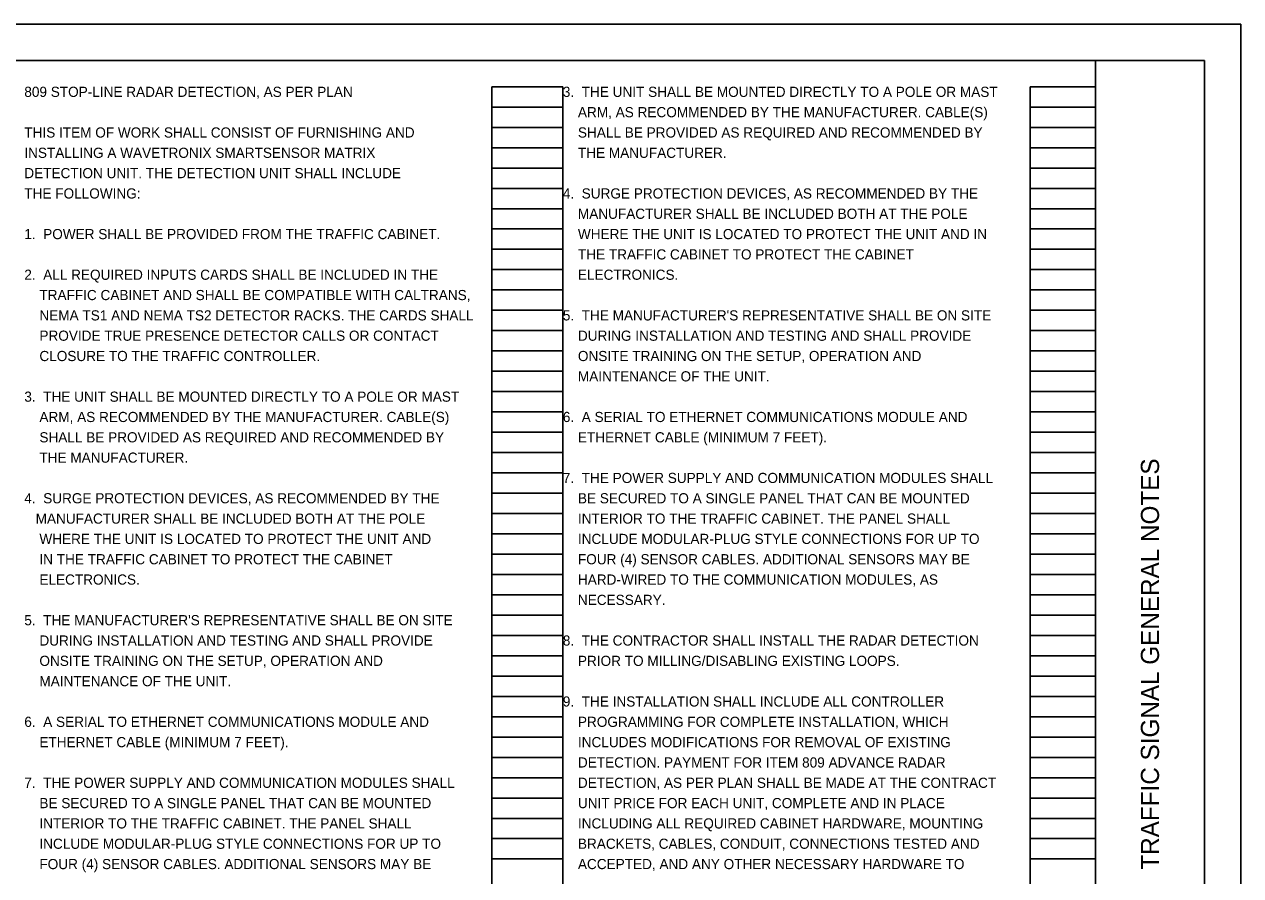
# Model space of a CAD drawing. Extents: x 0 to 34, y 0 to 22.
# Drawn here: x 17.24 to 34, y 10.27 to 22 of the extents above; entities that cross this region are included whole.
import ezdxf

# ---------------------------------------------------------------- set-up
doc = ezdxf.new("R2010")
doc.units = 0
for name, color, linetype in [('SH_Border', 7, 'Continuous'), ('SH_Cut_Line', 7, 'Continuous'), ('SH_Data', 7, 'Continuous'), ('SH_Text', 7, 'Continuous')]:
    doc.layers.add(name, color=color, linetype=linetype)

msp = doc.modelspace()

# ---------------------------------------------------------------- linework, layer by layer
at = {"layer": 'SH_Border'}
msp.add_line((32, 0.5), (32, 21.5), dxfattribs=at)
msp.add_lwpolyline([(1.5, 21.5), (33.5, 21.5), (33.5, 0.5), (1.5, 0.5)], close=True, dxfattribs=at)
at = {"layer": 'SH_Cut_Line'}
msp.add_lwpolyline([(0, 0), (34, 0), (34, 22), (0, 22)], close=True, dxfattribs=at)
at = {"layer": 'SH_Data'}
for p, q in [((23.68, 0.98), (23.68, 21.14)), ((23.68, 21.14), (24.66, 21.14)), ((24.66, 0.98), (24.66, 21.14)), ((31.1, 0.98), (31.1, 21.14)), ((31.1, 21.14), (32, 21.14)), ((32, 0.98), (32, 21.14)), ((23.68, 20.86), (24.66, 20.86)), ((31.1, 20.86), (32, 20.86)), ((23.68, 20.58), (24.66, 20.58)), ((31.1, 20.58), (32, 20.58)), ((23.68, 20.3), (24.66, 20.3)), ((31.1, 20.3), (32, 20.3)), ((23.68, 20.02), (24.66, 20.02)), ((31.1, 20.02), (32, 20.02)), ((23.68, 19.74), (24.66, 19.74)), ((31.1, 19.74), (32, 19.74)), ((23.68, 19.46), (24.66, 19.46)), ((31.1, 19.46), (32, 19.46)), ((23.68, 19.18), (24.66, 19.18)), ((31.1, 19.18), (32, 19.18)), ((23.68, 18.9), (24.66, 18.9)), ((31.1, 18.9), (32, 18.9)), ((23.68, 18.62), (24.66, 18.62)), ((31.1, 18.62), (32, 18.62)), ((23.68, 18.34), (24.66, 18.34)), ((31.1, 18.34), (32, 18.34)), ((23.68, 18.06), (24.66, 18.06)), ((31.1, 18.06), (32, 18.06)), ((23.68, 17.78), (24.66, 17.78)), ((31.1, 17.78), (32, 17.78)), ((23.68, 17.5), (24.66, 17.5)), ((31.1, 17.5), (32, 17.5)), ((23.68, 17.22), (24.66, 17.22)), ((31.1, 17.22), (32, 17.22)), ((23.68, 16.94), (24.66, 16.94)), ((31.1, 16.94), (32, 16.94)), ((23.68, 16.66), (24.66, 16.66)), ((31.1, 16.66), (32, 16.66)), ((23.68, 16.38), (24.66, 16.38)), ((31.1, 16.38), (32, 16.38)), ((23.68, 16.1), (24.66, 16.1)), ((31.1, 16.1), (32, 16.1)), ((23.68, 15.82), (24.66, 15.82)), ((31.1, 15.82), (32, 15.82)), ((23.68, 15.54), (24.66, 15.54)), ((31.1, 15.54), (32, 15.54)), ((23.68, 15.26), (24.66, 15.26)), ((31.1, 15.26), (32, 15.26)), ((23.68, 14.98), (24.66, 14.98)), ((31.1, 14.98), (32, 14.98)), ((23.68, 14.7), (24.66, 14.7)), ((31.1, 14.7), (32, 14.7)), ((23.68, 14.42), (24.66, 14.42)), ((31.1, 14.42), (32, 14.42)), ((23.68, 14.14), (24.66, 14.14)), ((31.1, 14.14), (32, 14.14)), ((23.68, 13.86), (24.66, 13.86)), ((31.1, 13.86), (32, 13.86)), ((23.68, 13.58), (24.66, 13.58)), ((31.1, 13.58), (32, 13.58)), ((23.68, 13.3), (24.66, 13.3)), ((31.1, 13.3), (32, 13.3)), ((23.68, 13.02), (24.66, 13.02)), ((31.1, 13.02), (32, 13.02)), ((23.68, 12.74), (24.66, 12.74)), ((31.1, 12.74), (32, 12.74)), ((23.68, 12.46), (24.66, 12.46)), ((31.1, 12.46), (32, 12.46)), ((23.68, 12.18), (24.66, 12.18)), ((31.1, 12.18), (32, 12.18)), ((23.68, 11.9), (24.66, 11.9)), ((31.1, 11.9), (32, 11.9)), ((23.68, 11.62), (24.66, 11.62)), ((31.1, 11.62), (32, 11.62)), ((23.68, 11.34), (24.66, 11.34)), ((31.1, 11.34), (32, 11.34)), ((23.68, 11.06), (24.66, 11.06)), ((31.1, 11.06), (32, 11.06)), ((23.68, 10.78), (24.66, 10.78)), ((31.1, 10.78), (32, 10.78)), ((23.68, 10.5), (24.66, 10.5)), ((31.1, 10.5), (32, 10.5))]:
    msp.add_line(p, q, dxfattribs=at)

# ---------------------------------------------------------------- texts
msp.add_text('TRAFFIC SIGNAL GENERAL NOTES', height=0.25, rotation=90, dxfattribs=at).set_placement((32.875, 10.353))
at = {"layer": 'SH_Text'}
for s, p in [('809 STOP-LINE RADAR DETECTION, AS PER PLAN', (17.24, 21)), ('3.  THE UNIT SHALL BE MOUNTED DIRECTLY TO A POLE OR MAST', (24.66, 21)), ('    ARM, AS RECOMMENDED BY THE MANUFACTURER. CABLE(S)', (24.66, 20.72)), ('THIS ITEM OF WORK SHALL CONSIST OF FURNISHING AND', (17.24, 20.44)), ('    SHALL BE PROVIDED AS REQUIRED AND RECOMMENDED BY', (24.66, 20.44)), ('INSTALLING A WAVETRONIX SMARTSENSOR MATRIX', (17.24, 20.16)), ('    THE MANUFACTURER.', (24.66, 20.16)), ('DETECTION UNIT. THE DETECTION UNIT SHALL INCLUDE', (17.24, 19.88)), ('THE FOLLOWING:', (17.24, 19.6)), ('4.  SURGE PROTECTION DEVICES, AS RECOMMENDED BY THE', (24.66, 19.6)), ('    MANUFACTURER SHALL BE INCLUDED BOTH AT THE POLE', (24.66, 19.32)), ('1.  POWER SHALL BE PROVIDED FROM THE TRAFFIC CABINET.', (17.24, 19.04)), ('    WHERE THE UNIT IS LOCATED TO PROTECT THE UNIT AND IN', (24.66, 19.04)), ('    THE TRAFFIC CABINET TO PROTECT THE CABINET', (24.66, 18.76)), ('2.  ALL REQUIRED INPUTS CARDS SHALL BE INCLUDED IN THE', (17.24, 18.48)), ('    ELECTRONICS.', (24.66, 18.48)), ('    TRAFFIC CABINET AND SHALL BE COMPATIBLE WITH CALTRANS,', (17.24, 18.2)), ('    NEMA TS1 AND NEMA TS2 DETECTOR RACKS. THE CARDS SHALL', (17.24, 17.92)), ("5.  THE MANUFACTURER'S REPRESENTATIVE SHALL BE ON SITE", (24.66, 17.92)), ('    PROVIDE TRUE PRESENCE DETECTOR CALLS OR CONTACT', (17.24, 17.64)), ('    DURING INSTALLATION AND TESTING AND SHALL PROVIDE', (24.66, 17.64)), ('    CLOSURE TO THE TRAFFIC CONTROLLER.', (17.24, 17.36)), ('    ONSITE TRAINING ON THE SETUP, OPERATION AND', (24.66, 17.36)), ('    MAINTENANCE OF THE UNIT.', (24.66, 17.08)), ('3.  THE UNIT SHALL BE MOUNTED DIRECTLY TO A POLE OR MAST', (17.24, 16.8)), ('    ARM, AS RECOMMENDED BY THE MANUFACTURER. CABLE(S)', (17.24, 16.52)), ('6.  A SERIAL TO ETHERNET COMMUNICATIONS MODULE AND', (24.66, 16.52)), ('    SHALL BE PROVIDED AS REQUIRED AND RECOMMENDED BY', (17.24, 16.24)), ('    ETHERNET CABLE (MINIMUM 7 FEET).', (24.66, 16.24)), ('    THE MANUFACTURER.', (17.24, 15.96)), ('7.  THE POWER SUPPLY AND COMMUNICATION MODULES SHALL', (24.66, 15.68)), ('4.  SURGE PROTECTION DEVICES, AS RECOMMENDED BY THE', (17.24, 15.4)), ('    BE SECURED TO A SINGLE PANEL THAT CAN BE MOUNTED', (24.66, 15.4)), ('   MANUFACTURER SHALL BE INCLUDED BOTH AT THE POLE', (17.24, 15.12)), ('    INTERIOR TO THE TRAFFIC CABINET. THE PANEL SHALL', (24.66, 15.12)), ('    WHERE THE UNIT IS LOCATED TO PROTECT THE UNIT AND', (17.24, 14.84)), ('    INCLUDE MODULAR-PLUG STYLE CONNECTIONS FOR UP TO', (24.66, 14.84)), ('    IN THE TRAFFIC CABINET TO PROTECT THE CABINET', (17.24, 14.56)), ('    FOUR (4) SENSOR CABLES. ADDITIONAL SENSORS MAY BE', (24.66, 14.56)), ('    ELECTRONICS.', (17.24, 14.28)), ('    HARD-WIRED TO THE COMMUNICATION MODULES, AS', (24.66, 14.28)), ('    NECESSARY.', (24.66, 14)), ("5.  THE MANUFACTURER'S REPRESENTATIVE SHALL BE ON SITE", (17.24, 13.72)), ('    DURING INSTALLATION AND TESTING AND SHALL PROVIDE', (17.24, 13.44)), ('8.  THE CONTRACTOR SHALL INSTALL THE RADAR DETECTION', (24.66, 13.44)), ('    ONSITE TRAINING ON THE SETUP, OPERATION AND', (17.24, 13.16)), ('    PRIOR TO MILLING/DISABLING EXISTING LOOPS.', (24.66, 13.16)), ('    MAINTENANCE OF THE UNIT.', (17.24, 12.88)), ('9.  THE INSTALLATION SHALL INCLUDE ALL CONTROLLER', (24.66, 12.6)), ('6.  A SERIAL TO ETHERNET COMMUNICATIONS MODULE AND', (17.24, 12.32)), ('    PROGRAMMING FOR COMPLETE INSTALLATION, WHICH', (24.66, 12.32)), ('    ETHERNET CABLE (MINIMUM 7 FEET).', (17.24, 12.04)), ('    INCLUDES MODIFICATIONS FOR REMOVAL OF EXISTING', (24.66, 12.04)), ('    DETECTION. PAYMENT FOR ITEM 809 ADVANCE RADAR', (24.66, 11.76)), ('7.  THE POWER SUPPLY AND COMMUNICATION MODULES SHALL', (17.24, 11.48)), ('    DETECTION, AS PER PLAN SHALL BE MADE AT THE CONTRACT', (24.66, 11.48)), ('    BE SECURED TO A SINGLE PANEL THAT CAN BE MOUNTED', (17.24, 11.2)), ('    UNIT PRICE FOR EACH UNIT, COMPLETE AND IN PLACE', (24.66, 11.2)), ('    INTERIOR TO THE TRAFFIC CABINET. THE PANEL SHALL', (17.24, 10.92)), ('    INCLUDING ALL REQUIRED CABINET HARDWARE, MOUNTING', (24.66, 10.92)), ('    INCLUDE MODULAR-PLUG STYLE CONNECTIONS FOR UP TO', (17.24, 10.64)), ('    BRACKETS, CABLES, CONDUIT, CONNECTIONS TESTED AND', (24.66, 10.64)), ('    FOUR (4) SENSOR CABLES. ADDITIONAL SENSORS MAY BE', (17.24, 10.36)), ('    ACCEPTED, AND ANY OTHER NECESSARY HARDWARE TO', (24.66, 10.36))]:
    msp.add_text(s, height=0.14, dxfattribs=at).set_placement(p)

doc.saveas('drawing.dxf')
